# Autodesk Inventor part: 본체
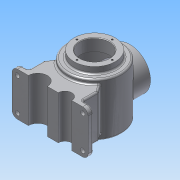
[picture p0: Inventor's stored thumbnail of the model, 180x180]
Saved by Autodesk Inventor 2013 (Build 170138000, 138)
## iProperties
Created: 2018-08
Part Number: 본체
Material: 알루미늄 6061
Document SubType Name: Modeling
Designer: Administrator
Density: 2.71 g/cm^3
Mass: 1885.08 g
Surface Area: 1089.76 cm^2
Volume: 695.603 cm^3
Author: Administrator
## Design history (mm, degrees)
sketch "스케치4"
  geometry: L1 (0, 160.215)-(0, -160.215); L2 (50, -102.762)-(50, -11); L3 (47, -8)-(41, -8); L4 (38, -5)-(38, 4); L5 (38, 4)-(0, 4); A1 r 116 centre (0, 0) between (0, -116) and (48.248, -105.49); A2 r 3 centre (47, -11) between (50, -11) and (47, -8); A3 r 3 centre (47, -102.762) between (48.248, -105.49) and (50, -102.762); A4 r 3 centre (41, -5) between (38, -5) and (41, -8); 5 further points
  constraints: 10 end point, 9 point on circle, 7 point on line, 6 tangent, 4 centre point, 2 coincident, 2 equal radius, 2 parallel, 2 perpendicular, 1 midpoint, 1 vertical
  dimensions: "d31" = 100 diameter of L2 L1; "d32" = 76 diameter of L4 L1; "d33" = 116 radius of A1; "d34" = 108 distance from line of A1.start L3; "d35" = 12 distance of point (38, -8) L4.end; "d39" = 3 radius of A2
revolve "회전3" sketch "스케치4" stored, may be unused: angle "d38" = 90 deg
sketch "스케치5"
  geometry: L1 (50, -11)-(50, -102.762) reference; L2 (-47, -8)-(47, -8) reference; L3 (40, -21)-(40, -96.125); L4 (37, -18)-(27, -18); L5 (0, 252.733)-(0, -252.733); L6 (27, -18)-(27, 4); L7 (-38, 4)-(38, 4) reference; L8 (27, 4)-(0, 4); A1 r 116 centre (0, 0) between (-48.248, -105.49) and (48.248, -105.49) reference; A2 r 3 centre (47, -102.762) between (48.248, -105.49) and (50, -102.762) reference; A3 r 3 centre (47, -11) between (50, -11) and (47, -8) reference; A4 r 106 centre (0, 0) between (0, -106) and (38.078, -98.925); A5 r 3 centre (37, -21) between (40, -21) and (37, -18); A6 r 3 centre (37, -96.125) between (38.078, -98.925) and (40, -96.125); 4 further points
  constraints: 10 end point, 7 point on circle, 5 point on line, 4 tangent, 3 centre point, 2 collinear, 2 parallel, 2 perpendicular, 1 coincident, 1 equal radius, 1 midpoint
  dimensions: "d41" = 10 distance between parallel lines of L1 L3; "d42" = 10 radial gap between concentric circles of A1 A4; "d43" = 10 distance between parallel lines of L2 L4; "d44" = 54 diameter of L6 L5; "d46" = 3 radius of A5
revolve "회전4" sketch "스케치5" stored, may be unused: angle "d45" = 90 deg
node "작업 평면1"
sketch "스케치6"
  geometry: L1 (-60, -16)-(60, -16); L2 (70, -26)-(70, -86); L3 (60, -96)-(-60, -96); L4 (-70, -86)-(-70, -26); L5 (-70, -16)-(70, -96); L6 (70, -16)-(-70, -96); L7 (-47, -8)-(47, -8) reference; C1 r 4 at (60, -26); C2 r 4 at (60, -86); C3 r 4 at (-60, -26); C4 r 4 at (-60, -86); A1 r 10 centre (60, -26) between (70, -26) and (60, -16); A2 r 10 centre (60, -86) between (60, -96) and (70, -86); A3 r 10 centre (-60, -86) between (-70, -86) and (-60, -96); A4 r 10 centre (-60, -26) between (-60, -16) and (-70, -26); 3 further points
  constraints: 12 end point, 8 centre point, 8 point on circle, 8 point on line, 8 tangent, 4 coincident, 3 midpoint, 2 equal radius, 2 parallel, 1 horizontal, 1 perpendicular, 1 vertical alignment
  dimensions: "d48" = 140 distance of L5.end L6.end; "d49" = 80 distance of L6.start L5.end; "d50" = 10 radius of A1; "d51" = 10 radius of A4; "d52" = 8 distance between parallel lines of L1 L7; "d53" = 8 diameter of C1; "d54" = 8 diameter of C2; "d55" = 8 diameter of C3; "d56" = 8 diameter of C4
extrude "돌출1" join sketch "스케치6" distance "d57" = 10; taper "d58" = 0 deg
sketch "스케치7"
  geometry: L1 (0, 10)-(120, 10) reference; L2 (-10, 0)-(-10, 10) reference; L3 (130, 0)-(130, 10) reference; L4 (130, 10)-(120, 10) reference; L5 (0, 10)-(-10, 10) reference; L6 (-10, 10)-(19.696, 52.41); L7 (130, 10)-(100.304, 52.41); L8 (-10, 10)-(130, 10); C1 r 50 at (60, 82) reference; A1 r 50 centre (60, 82) between (19.696, 52.41) and (100.304, 52.41); 1 further point
  constraints: 6 end point, 2 collinear, 2 point on circle, 2 point on line, 1 centre point, 1 coincident, 1 concentric
  dimensions: "d65" = 35 deg angle of L6 L2; "d66" = 35 deg angle of L7 L3
extrude "돌출2" join sketch "스케치7" distance "d67" = 80; taper "d68" = 0 deg
sketch "스케치8"
  geometry: L1 (130, 10)-(100.304, 52.41) reference; L2 (19.696, 52.41)-(-10, 10) reference; L3 (-10, 0)-(-10, 10) reference; L4 (130, 0)-(130, 10) reference; L5 (-10, 10)-(10, 10); L6 (10, 10)-(10, 38.563); L7 (10, 38.563)-(-10, 38.563); L8 (-10, 38.563)-(-10, 10); L9 (130, 10)-(110, 10); L10 (110, 10)-(110, 38.563); L11 (110, 38.563)-(130, 38.563); L12 (130, 38.563)-(130, 10)
  constraints: 16 end point, 4 parallel, 2 horizontal, 2 perpendicular, 2 point on line
  dimensions: "d69" = 20 distance of L2.end L5.end; "d70" = 20 distance of L1.start L9.end
extrude "돌출3" cut sketch "스케치8" stored distance "d71" = 80; taper "d72" = 0 deg
sketch "스케치9"
  geometry: L1 (120, 0)-(0, 0) reference; L2 (-10, 0)-(-10, 10) reference; L3 (130, 0)-(130, 10) reference; L4 (60, 82)-(60, -47.486); C1 r 17.5 at (82.5, 0); C2 r 12.5 at (32.5, 0); A1 r 50 centre (60, 82) between (19.696, 52.41) and (100.304, 52.41) reference
  constraints: 2 centre point, 2 end point, 2 point on line, 1 coincident, 1 parallel
  dimensions: "d73" = 22.5 distance from line of L4 C1.centre; "d75" = 27.5 distance from line of C2.centre L4; "d76" = 35 diameter of C1; "d77" = 25 diameter of C2
extrude "돌출4" cut sketch "스케치9" stored distance "d78" = 80; taper "d79" = 0 deg
node "작업 평면3"
sketch "스케치10"
  geometry: L1 (70, -86)-(70, -26) reference; L2 (-47, -8)-(47, -8) reference; C1 r 38 at (0, -58); 1 further point
  constraints: 1 centre point, 1 vertical alignment
  dimensions: "d84" = 76 diameter of C1; "d128" = 50 distance from line of C1.centre L2
extrude "돌출5" join sketch "스케치10" stored distance "d85" = 80; taper "d86" = 0 deg
hole "구멍1" diameter "d89" = 54; stored, may be unused: countersink angle "d93" = 90 deg, drill point angle "d95" = 0 deg; dims "d87" = 10, "d88" = 10, "d90" = 6, "d91" = 4, "d92" = 2, "d94" = 8
sketch "스케치11"
  geometry: C1 r 27 at (0, 0) reference; 2 further points
  constraints: 1 horizontal alignment
  dimensions: "d97" = 32.5 distance of C1.centre point (-32.5, 0)
hole "구멍2" sketch "스케치11" at (-32.5, 0) diameter "d98" = 3.242; stored, may be unused: countersink angle "d102" = 90 deg, drill point angle "d104" = 118 deg; dims "d99" = 8, "d100" = 4, "d101" = 2, "d103" = 10
sketch "스케치12"
  geometry: C1 r 27 at (0, 0) reference; 1 further point
  constraints: 1 vertical alignment
  dimensions: "d108" = 32.5 distance of C1.centre point (0, 32.5)
hole "구멍3" sketch "스케치12" at (0, 32.5) diameter "d109" = 3.242; stored, may be unused: countersink angle "d113" = 90 deg, drill point angle "d115" = 118 deg; dims "d110" = 8, "d111" = 4, "d112" = 2, "d114" = 10
chamfer "모따기1" distance "d119" = 1; stored, may be unused: second distance "d120" = 2, angle "d121" = 45 deg
node "작업 평면4"
sketch "스케치13"
  geometry: C1 r 32.5 at (0, 0); 1 further point
  constraints: 1 centre point, 1 coincident, 1 other
  dimensions: "d122" = 65 diameter of C1
feature "엠보싱2" sketch "스케치13" dims "d125" = 0.5, "d126" = 0
fillet "모깎기6" dims "d130" = 3
fillet "모깎기7" dims "d131" = 3
node "솔리드2"
pattern_circular "원형 패턴1" dims angle "d106" = 360 deg
pattern_circular "원형 패턴2" dims angle "d117" = 360 deg
other parameters: "d0" = 232, "d23" = 10, "d30" = 232, "d47" = -82, "d83" = 65
